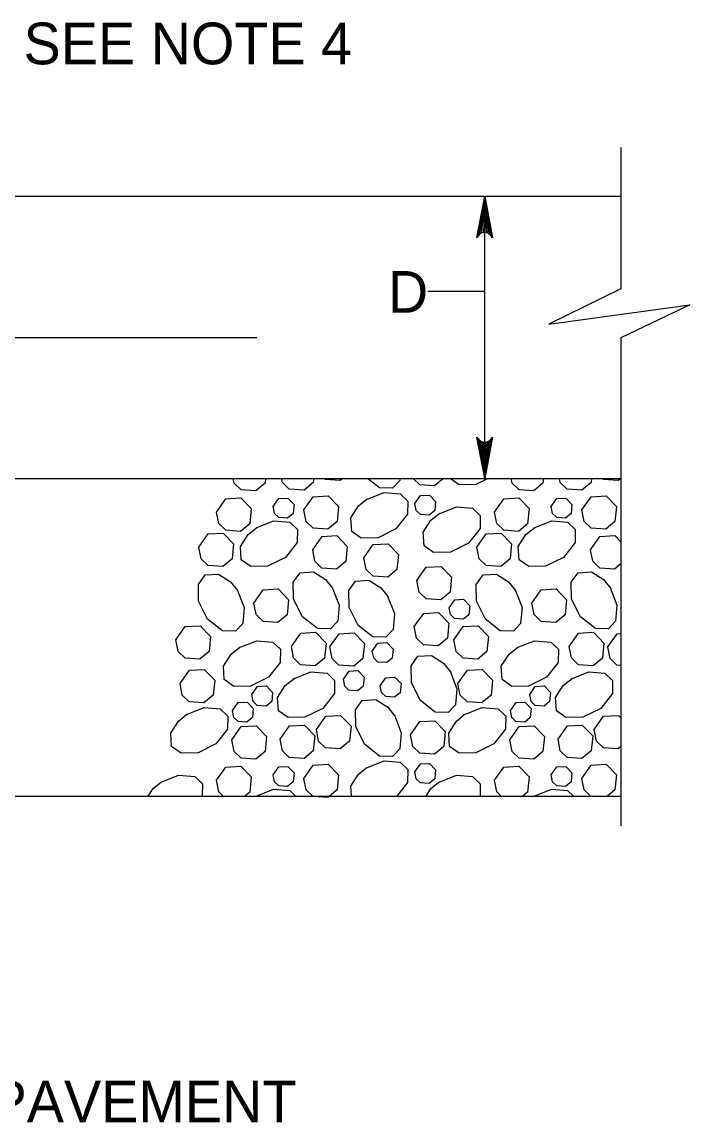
# Model space of a CAD drawing. Extents: x 2084213 to 2099800, y 976677 to 981262.
# Drawn here: x 2095747 to 2095904.6, y 979121.1 to 979381.1 of the extents above; entities that cross this region are included whole.
import ezdxf

# ---------------------------------------------------------------- set-up
doc = ezdxf.new("R2010")
doc.units = 0
doc.layers.add('1', color=7, linetype='Continuous')

msp = doc.modelspace()

# ---------------------------------------------------------------- linework, layer by layer
at = {"layer": '1'}
for p, q in [((2095888.3, 979351.47), (2095888.3, 979318.12)), ((2095516.44, 979339.99), (2095888.3, 979339.99)), ((2095856.17, 979273.33), (2095856.17, 979339.99)), ((2095856.17, 979317.49), (2095842.7, 979317.47)), ((2095602.37, 979306.66), (2095802.37, 979306.66)), ((2095888.3, 979306.58), (2095888.3, 979191.31)), ((2095516.44, 979273.33), (2095888.3, 979273.33)), ((2095516.44, 979198.33), (2095888.3, 979198.33))]:
    msp.add_line(p, q, dxfattribs=at)
for points in [[(2095856.17, 979339.99), (2095858, 979330.2), (2095857.74, 979330.58), (2095857.48, 979330.96), (2095857.15, 979331.15), (2095856.82, 979331.35), (2095856.49, 979331.4), (2095856.17, 979331.46), (2095855.84, 979331.4), (2095855.51, 979331.35), (2095855.18, 979331.15), (2095854.85, 979330.96), (2095854.59, 979330.58), (2095854.33, 979330.2), (2095856.17, 979339.99), (2095854.59, 979330.58), (2095854.85, 979330.96), (2095856.17, 979339.99), (2095855.18, 979331.15), (2095855.51, 979331.35), (2095856.17, 979339.99), (2095855.84, 979331.4), (2095856.17, 979331.46), (2095856.17, 979339.99), (2095856.49, 979331.4), (2095856.82, 979331.35), (2095856.17, 979339.99), (2095857.15, 979331.15), (2095857.48, 979330.96), (2095856.17, 979339.99), (2095857.74, 979330.58)], [(2095888.3, 979318.12), (2095871.29, 979309.8), (2095904.59, 979314.33), (2095888.3, 979306.58)], [(2095856.17, 979273.33), (2095854.33, 979283.11), (2095854.59, 979282.74), (2095854.85, 979282.36), (2095855.18, 979282.17), (2095855.51, 979281.97), (2095855.84, 979281.91), (2095856.17, 979281.86), (2095856.49, 979281.91), (2095856.82, 979281.97), (2095857.15, 979282.17), (2095857.48, 979282.36), (2095857.74, 979282.74), (2095858, 979283.11), (2095856.17, 979273.33), (2095857.74, 979282.74), (2095857.48, 979282.36), (2095856.17, 979273.33), (2095857.15, 979282.17), (2095856.82, 979281.97), (2095856.17, 979273.33), (2095856.49, 979281.91), (2095856.17, 979281.86), (2095856.17, 979273.33), (2095855.84, 979281.91), (2095855.51, 979281.97), (2095856.17, 979273.33), (2095855.18, 979282.17), (2095854.85, 979282.36), (2095856.17, 979273.33), (2095854.59, 979282.74)], [(2095804.43, 979273.33), (2095804.32, 979272.22), (2095802.15, 979270.41), (2095798.67, 979270.67), (2095797.03, 979272.25), (2095796.82, 979273.33)], [(2095815.8, 979273.33), (2095815.7, 979272.35), (2095813.53, 979270.54), (2095810.05, 979270.8), (2095808.41, 979272.38), (2095808.23, 979273.33)], [(2095822.66, 979273.33), (2095822.08, 979272.85), (2095818.6, 979273.1), (2095818.37, 979273.33)], [(2095836.19, 979273.33), (2095836.14, 979272.86), (2095834.43, 979271.05), (2095831.36, 979271.11), (2095828.52, 979273.33)], [(2095846.42, 979273.33), (2095844.32, 979271.58), (2095840.84, 979271.83), (2095839.3, 979273.33)], [(2095856.96, 979273.33), (2095854.1, 979271.89), (2095850.11, 979271.82), (2095848, 979273.33)], [(2095870.01, 979273.33), (2095869.9, 979272.22), (2095867.73, 979270.41), (2095864.25, 979270.67), (2095862.61, 979272.25), (2095862.4, 979273.33)], [(2095881.38, 979273.33), (2095881.28, 979272.35), (2095879.11, 979270.54), (2095875.63, 979270.8), (2095873.99, 979272.38), (2095873.81, 979273.33)], [(2095888.24, 979273.33), (2095887.66, 979272.85), (2095884.18, 979273.1), (2095883.95, 979273.33)], [(2095792.88, 979265.41), (2095795.09, 979268.55), (2095798.61, 979268.75), (2095801.06, 979266.22), (2095800.7, 979262.66), (2095798.53, 979260.85), (2095795.05, 979261.1), (2095793.42, 979262.69), (2095792.88, 979265.41)], [(2095806.27, 979266.71), (2095807.59, 979268.59), (2095809.7, 979268.71), (2095811.17, 979267.18), (2095810.96, 979265.05), (2095809.65, 979263.97), (2095807.57, 979264.12), (2095806.59, 979265.07), (2095806.27, 979266.7)], [(2095813.49, 979265.89), (2095815.7, 979269.03), (2095819.22, 979269.23), (2095821.67, 979266.69), (2095821.31, 979263.14), (2095819.14, 979261.33), (2095815.66, 979261.58), (2095814.03, 979263.16), (2095813.5, 979265.89)], [(2095828.29, 979268.4), (2095832.42, 979270.04), (2095836.21, 979269.71), (2095838.01, 979268), (2095837.96, 979264.92), (2095835.22, 979261.43), (2095831, 979259.31), (2095827.01, 979259.24), (2095824.77, 979260.84), (2095824.56, 979264.01), (2095826.38, 979266.85), (2095828.46, 979268.51)], [(2095839.68, 979267.43), (2095841, 979269.31), (2095843.12, 979269.43), (2095844.58, 979267.91), (2095844.37, 979265.78), (2095843.07, 979264.69), (2095840.98, 979264.84), (2095840, 979265.79), (2095839.68, 979267.43)], [(2095858.46, 979265.41), (2095860.67, 979268.55), (2095864.19, 979268.75), (2095866.64, 979266.22), (2095866.28, 979262.66), (2095864.11, 979260.85), (2095860.63, 979261.1), (2095859, 979262.69), (2095858.46, 979265.41)], [(2095871.84, 979266.71), (2095873.17, 979268.59), (2095875.28, 979268.71), (2095876.75, 979267.18), (2095876.54, 979265.05), (2095875.23, 979263.97), (2095873.15, 979264.12), (2095872.16, 979265.07), (2095871.85, 979266.7)], [(2095879.07, 979265.89), (2095881.28, 979269.03), (2095884.8, 979269.23), (2095887.25, 979266.69), (2095886.89, 979263.14), (2095884.72, 979261.33), (2095881.24, 979261.58), (2095879.61, 979263.16), (2095879.08, 979265.89)], [(2095845.39, 979265.01), (2095849.52, 979266.65), (2095853.31, 979266.32), (2095855.11, 979264.61), (2095855.06, 979261.53), (2095852.32, 979258.04), (2095848.1, 979255.93), (2095844.11, 979255.86), (2095841.87, 979257.45), (2095841.66, 979260.62), (2095843.48, 979263.46), (2095845.56, 979265.12)], [(2095802.23, 979261.68), (2095806.36, 979263.31), (2095810.15, 979262.99), (2095811.95, 979261.27), (2095811.89, 979258.2), (2095809.16, 979254.7), (2095804.93, 979252.59), (2095800.95, 979252.52), (2095798.71, 979254.11), (2095798.5, 979257.29), (2095800.32, 979260.12), (2095802.4, 979261.78)], [(2095867.81, 979261.68), (2095871.94, 979263.31), (2095875.73, 979262.99), (2095877.53, 979261.27), (2095877.47, 979258.2), (2095874.74, 979254.7), (2095870.51, 979252.59), (2095866.53, 979252.52), (2095864.29, 979254.11), (2095864.08, 979257.29), (2095865.89, 979260.12), (2095867.98, 979261.78)], [(2095788.73, 979257.11), (2095790.94, 979260.25), (2095794.46, 979260.45), (2095796.91, 979257.91), (2095796.55, 979254.36), (2095794.38, 979252.55), (2095790.9, 979252.8), (2095789.27, 979254.39), (2095788.73, 979257.11)], [(2095854.31, 979257.11), (2095856.52, 979260.25), (2095860.04, 979260.45), (2095862.49, 979257.91), (2095862.13, 979254.36), (2095859.96, 979252.55), (2095856.48, 979252.8), (2095854.85, 979254.39), (2095854.31, 979257.11)], [(2095815.57, 979256.5), (2095817.77, 979259.64), (2095821.3, 979259.84), (2095823.74, 979257.3), (2095823.39, 979253.74), (2095821.21, 979251.93), (2095817.74, 979252.18), (2095816.1, 979253.77), (2095815.57, 979256.5)], [(2095827.63, 979254.58), (2095829.83, 979257.71), (2095833.36, 979257.92), (2095835.8, 979255.38), (2095835.45, 979251.82), (2095833.27, 979250.01), (2095829.8, 979250.26), (2095828.16, 979251.85), (2095827.63, 979254.58)], [(2095881.15, 979256.5), (2095883.35, 979259.64), (2095886.88, 979259.84), (2095888.3, 979258.36)], [(2095888.3, 979253.19), (2095886.79, 979251.93), (2095883.32, 979252.18), (2095881.68, 979253.77), (2095881.15, 979256.5)], [(2095840.17, 979249.24), (2095842.37, 979252.38), (2095845.89, 979252.58), (2095848.34, 979250.04), (2095847.99, 979246.49), (2095845.81, 979244.68), (2095842.34, 979244.93), (2095840.7, 979246.52), (2095840.17, 979249.24)], [(2095797.74, 979247.03), (2095799.38, 979242.9), (2095799.05, 979239.11), (2095797.34, 979237.31), (2095794.26, 979237.37), (2095790.77, 979240.1), (2095788.66, 979244.33), (2095788.59, 979248.31), (2095790.18, 979250.55), (2095793.35, 979250.76), (2095796.19, 979248.94), (2095797.85, 979246.86)], [(2095820.16, 979247.56), (2095821.8, 979243.43), (2095821.47, 979239.64), (2095819.75, 979237.84), (2095816.68, 979237.9), (2095813.18, 979240.63), (2095811.07, 979244.86), (2095811, 979248.84), (2095812.59, 979251.08), (2095815.77, 979251.3), (2095818.6, 979249.48), (2095820.26, 979247.39)], [(2095863.32, 979247.03), (2095864.96, 979242.9), (2095864.63, 979239.11), (2095862.92, 979237.31), (2095859.84, 979237.37), (2095856.35, 979240.1), (2095854.23, 979244.33), (2095854.16, 979248.31), (2095855.76, 979250.55), (2095858.93, 979250.76), (2095861.77, 979248.94), (2095863.43, 979246.86)], [(2095885.74, 979247.56), (2095887.37, 979243.43), (2095887.05, 979239.64), (2095885.33, 979237.84), (2095882.26, 979237.9), (2095878.76, 979240.63), (2095876.65, 979244.86), (2095876.58, 979248.84), (2095878.17, 979251.08), (2095881.35, 979251.3), (2095884.18, 979249.48), (2095885.84, 979247.39)], [(2095833.24, 979245.56), (2095834.87, 979241.43), (2095834.54, 979237.64), (2095832.83, 979235.84), (2095829.76, 979235.9), (2095826.26, 979238.63), (2095824.15, 979242.86), (2095824.08, 979246.84), (2095825.67, 979249.08), (2095828.84, 979249.29), (2095831.68, 979247.48), (2095833.34, 979245.39)], [(2095801.71, 979243.91), (2095803.91, 979247.04), (2095807.43, 979247.24), (2095809.88, 979244.71), (2095809.53, 979241.15), (2095807.35, 979239.34), (2095803.87, 979239.59), (2095802.24, 979241.18), (2095801.71, 979243.91)], [(2095847.75, 979242.81), (2095849.07, 979244.7), (2095851.18, 979244.82), (2095852.65, 979243.29), (2095852.44, 979241.16), (2095851.13, 979240.07), (2095849.05, 979240.23), (2095848.07, 979241.18), (2095847.75, 979242.81)], [(2095867.28, 979243.91), (2095869.49, 979247.04), (2095873.01, 979247.24), (2095875.46, 979244.71), (2095875.11, 979241.15), (2095872.93, 979239.34), (2095869.45, 979239.59), (2095867.82, 979241.18), (2095867.29, 979243.91)], [(2095839.55, 979238.35), (2095841.76, 979241.48), (2095845.28, 979241.69), (2095847.73, 979239.15), (2095847.37, 979235.59), (2095845.2, 979233.78), (2095841.72, 979234.03), (2095840.08, 979235.62), (2095839.55, 979238.35)], [(2095783.29, 979235.23), (2095785.5, 979238.37), (2095789.02, 979238.57), (2095791.47, 979236.03), (2095791.11, 979232.48), (2095788.94, 979230.67), (2095785.46, 979230.92), (2095783.82, 979232.5), (2095783.29, 979235.23)], [(2095810.53, 979233.68), (2095812.74, 979236.82), (2095816.26, 979237.02), (2095818.71, 979234.48), (2095818.35, 979230.92), (2095816.18, 979229.11), (2095812.7, 979229.36), (2095811.07, 979230.95), (2095810.53, 979233.68)], [(2095819.61, 979233.54), (2095821.81, 979236.68), (2095825.33, 979236.88), (2095827.78, 979234.34), (2095827.43, 979230.79), (2095825.25, 979228.98), (2095821.77, 979229.23), (2095820.14, 979230.82), (2095819.61, 979233.54)], [(2095848.87, 979235.23), (2095851.08, 979238.37), (2095854.6, 979238.57), (2095857.05, 979236.03), (2095856.69, 979232.48), (2095854.52, 979230.67), (2095851.04, 979230.92), (2095849.4, 979232.5), (2095848.87, 979235.23)], [(2095876.11, 979233.68), (2095878.32, 979236.82), (2095881.84, 979237.02), (2095884.29, 979234.48), (2095883.93, 979230.92), (2095881.76, 979229.11), (2095878.28, 979229.36), (2095876.64, 979230.95), (2095876.11, 979233.68)], [(2095798.23, 979233.39), (2095802.35, 979235.03), (2095806.15, 979234.7), (2095807.95, 979232.99), (2095807.89, 979229.91), (2095805.16, 979226.42), (2095800.93, 979224.3), (2095796.95, 979224.23), (2095794.71, 979225.83), (2095794.49, 979229), (2095796.31, 979231.83), (2095798.39, 979233.5)], [(2095829.64, 979232.58), (2095830.96, 979234.46), (2095833.08, 979234.58), (2095834.55, 979233.05), (2095834.33, 979230.92), (2095833.03, 979229.84), (2095830.94, 979229.99), (2095829.96, 979230.94), (2095829.64, 979232.57)], [(2095863.81, 979233.39), (2095867.93, 979235.03), (2095871.72, 979234.7), (2095873.53, 979232.99), (2095873.47, 979229.91), (2095870.73, 979226.42), (2095866.51, 979224.3), (2095862.53, 979224.23), (2095860.28, 979225.83), (2095860.07, 979229), (2095861.89, 979231.83), (2095863.97, 979233.5)], [(2095885.18, 979233.54), (2095887.39, 979236.68), (2095888.3, 979236.73)], [(2095888.3, 979229.16), (2095887.35, 979229.23), (2095885.72, 979230.82), (2095885.19, 979233.54)], [(2095847.98, 979227.81), (2095849.61, 979223.69), (2095849.29, 979219.9), (2095847.57, 979218.1), (2095844.5, 979218.15), (2095841, 979220.89), (2095838.89, 979225.11), (2095838.82, 979229.09), (2095840.41, 979231.34), (2095843.59, 979231.55), (2095846.42, 979229.73), (2095848.08, 979227.65)], [(2095784.27, 979224.91), (2095786.48, 979228.05), (2095790, 979228.25), (2095792.45, 979225.71), (2095792.09, 979222.15), (2095789.92, 979220.34), (2095786.44, 979220.6), (2095784.81, 979222.18), (2095784.27, 979224.91)], [(2095811.03, 979226.02), (2095815.16, 979227.66), (2095818.95, 979227.33), (2095820.75, 979225.62), (2095820.69, 979222.54), (2095817.96, 979219.04), (2095813.73, 979216.93), (2095809.75, 979216.86), (2095807.51, 979218.45), (2095807.3, 979221.63), (2095809.11, 979224.46), (2095811.2, 979226.13)], [(2095822.81, 979225.95), (2095824.14, 979227.84), (2095826.25, 979227.96), (2095827.72, 979226.44), (2095827.51, 979224.3), (2095826.2, 979223.22), (2095824.12, 979223.37), (2095823.13, 979224.32), (2095822.82, 979225.95)], [(2095849.85, 979224.91), (2095852.06, 979228.05), (2095855.58, 979228.25), (2095858.03, 979225.71), (2095857.67, 979222.15), (2095855.5, 979220.34), (2095852.02, 979220.6), (2095850.38, 979222.18), (2095849.85, 979224.91)], [(2095876.61, 979226.02), (2095880.74, 979227.66), (2095884.53, 979227.33), (2095886.33, 979225.62), (2095886.27, 979222.54), (2095883.54, 979219.04), (2095879.31, 979216.93), (2095875.33, 979216.86), (2095873.09, 979218.45), (2095872.87, 979221.63), (2095874.69, 979224.46), (2095876.78, 979226.13)], [(2095801.2, 979222.34), (2095802.52, 979224.22), (2095804.64, 979224.34), (2095806.1, 979222.82), (2095805.89, 979220.68), (2095804.59, 979219.6), (2095802.5, 979219.75), (2095801.52, 979220.7), (2095801.2, 979222.34)], [(2095831.5, 979224.4), (2095832.83, 979226.29), (2095834.94, 979226.41), (2095836.41, 979224.88), (2095836.2, 979222.75), (2095834.89, 979221.66), (2095832.8, 979221.82), (2095831.82, 979222.77), (2095831.5, 979224.4)], [(2095866.78, 979222.34), (2095868.1, 979224.22), (2095870.21, 979224.34), (2095871.68, 979222.82), (2095871.47, 979220.68), (2095870.16, 979219.6), (2095868.08, 979219.75), (2095867.1, 979220.7), (2095866.78, 979222.34)], [(2095785.81, 979217.61), (2095789.94, 979219.25), (2095793.73, 979218.92), (2095795.53, 979217.21), (2095795.47, 979214.13), (2095792.74, 979210.64), (2095788.52, 979208.53), (2095784.53, 979208.46), (2095782.29, 979210.05), (2095782.08, 979213.22), (2095783.9, 979216.06), (2095785.98, 979217.72)], [(2095796.65, 979218.51), (2095797.97, 979220.39), (2095800.08, 979220.51), (2095801.55, 979218.99), (2095801.34, 979216.86), (2095800.04, 979215.77), (2095797.95, 979215.92), (2095796.97, 979216.87), (2095796.65, 979218.51)], [(2095834.84, 979217.4), (2095836.47, 979213.28), (2095836.14, 979209.49), (2095834.43, 979207.69), (2095831.36, 979207.74), (2095827.86, 979210.48), (2095825.75, 979214.7), (2095825.68, 979218.69), (2095827.27, 979220.93), (2095830.44, 979221.14), (2095833.28, 979219.32), (2095834.94, 979217.24)], [(2095851.39, 979217.61), (2095855.52, 979219.25), (2095859.31, 979218.92), (2095861.11, 979217.21), (2095861.05, 979214.13), (2095858.32, 979210.64), (2095854.1, 979208.53), (2095850.11, 979208.46), (2095847.87, 979210.05), (2095847.66, 979213.22), (2095849.48, 979216.06), (2095851.56, 979217.72)], [(2095862.23, 979218.51), (2095863.55, 979220.39), (2095865.66, 979220.51), (2095867.13, 979218.99), (2095866.92, 979216.86), (2095865.61, 979215.77), (2095863.53, 979215.92), (2095862.55, 979216.87), (2095862.23, 979218.51)], [(2095816.43, 979214.04), (2095818.64, 979217.18), (2095822.16, 979217.38), (2095824.61, 979214.84), (2095824.26, 979211.29), (2095822.08, 979209.48), (2095818.6, 979209.73), (2095816.97, 979211.32), (2095816.44, 979214.04)], [(2095838.67, 979212.78), (2095840.88, 979215.92), (2095844.4, 979216.12), (2095846.85, 979213.58), (2095846.5, 979210.02), (2095844.32, 979208.21), (2095840.84, 979208.46), (2095839.21, 979210.05), (2095838.68, 979212.78)], [(2095882.01, 979214.04), (2095884.22, 979217.18), (2095887.74, 979217.38), (2095888.3, 979216.8)], [(2095796.5, 979211.61), (2095798.71, 979214.75), (2095802.23, 979214.95), (2095804.68, 979212.41), (2095804.32, 979208.86), (2095802.15, 979207.05), (2095798.67, 979207.3), (2095797.03, 979208.89), (2095796.5, 979211.61)], [(2095807.88, 979211.74), (2095810.09, 979214.88), (2095813.61, 979215.08), (2095816.06, 979212.54), (2095815.7, 979208.99), (2095813.53, 979207.18), (2095810.05, 979207.43), (2095808.41, 979209.02), (2095807.88, 979211.74)], [(2095862.08, 979211.61), (2095864.29, 979214.75), (2095867.81, 979214.95), (2095870.26, 979212.41), (2095869.9, 979208.86), (2095867.73, 979207.05), (2095864.25, 979207.3), (2095862.61, 979208.89), (2095862.08, 979211.61)], [(2095873.46, 979211.74), (2095875.67, 979214.88), (2095879.19, 979215.08), (2095881.63, 979212.54), (2095881.28, 979208.99), (2095879.11, 979207.18), (2095875.63, 979207.43), (2095873.99, 979209.02), (2095873.46, 979211.74)], [(2095888.3, 979210.01), (2095887.66, 979209.48), (2095884.18, 979209.73), (2095882.55, 979211.32), (2095882.02, 979214.04)], [(2095813.49, 979202.52), (2095815.7, 979205.66), (2095819.22, 979205.86), (2095821.67, 979203.33), (2095821.31, 979199.77), (2095819.14, 979197.96), (2095815.66, 979198.21), (2095814.03, 979199.8), (2095813.5, 979202.52)], [(2095828.29, 979205.03), (2095832.42, 979206.67), (2095836.21, 979206.34), (2095838.01, 979204.63), (2095837.96, 979201.55), (2095835.43, 979198.33)], [(2095839.68, 979204.06), (2095841, 979205.94), (2095843.12, 979206.06), (2095844.58, 979204.54), (2095844.37, 979202.41), (2095843.07, 979201.32), (2095840.98, 979201.47), (2095840, 979202.43), (2095839.68, 979204.06)], [(2095879.07, 979202.52), (2095881.28, 979205.66), (2095884.8, 979205.86), (2095887.25, 979203.33), (2095886.89, 979199.77), (2095885.16, 979198.33)], [(2095779.82, 979201.65), (2095783.94, 979203.28), (2095787.73, 979202.95), (2095789.53, 979201.24), (2095789.48, 979198.33)], [(2095792.88, 979202.05), (2095795.09, 979205.19), (2095798.61, 979205.39), (2095801.06, 979202.85), (2095800.7, 979199.29), (2095799.55, 979198.33)], [(2095806.27, 979203.34), (2095807.59, 979205.22), (2095809.7, 979205.34), (2095811.17, 979203.82), (2095810.96, 979201.68), (2095809.65, 979200.6), (2095807.57, 979200.75), (2095806.59, 979201.7), (2095806.27, 979203.34)], [(2095824.72, 979198.33), (2095824.56, 979200.64), (2095826.38, 979203.48), (2095828.46, 979205.14)], [(2095845.39, 979201.65), (2095849.52, 979203.28), (2095853.31, 979202.95), (2095855.11, 979201.24), (2095855.06, 979198.33)], [(2095858.46, 979202.05), (2095860.67, 979205.19), (2095864.19, 979205.39), (2095866.64, 979202.85), (2095866.28, 979199.29), (2095865.13, 979198.33)], [(2095871.84, 979203.34), (2095873.17, 979205.22), (2095875.28, 979205.34), (2095876.75, 979203.82), (2095876.54, 979201.68), (2095875.23, 979200.6), (2095873.15, 979200.75), (2095872.16, 979201.7), (2095871.85, 979203.34)], [(2095776.77, 979198.33), (2095777.9, 979200.09), (2095779.98, 979201.75)], [(2095794.44, 979198.33), (2095793.42, 979199.32), (2095792.88, 979202.05)], [(2095842.35, 979198.33), (2095843.48, 979200.09), (2095845.56, 979201.75)], [(2095860.02, 979198.33), (2095859, 979199.32), (2095858.46, 979202.05)], [(2095881.12, 979198.33), (2095879.61, 979199.8), (2095879.08, 979202.52)], [(2095802.23, 979198.31), (2095806.36, 979199.95), (2095810.15, 979199.62), (2095811.5, 979198.33)], [(2095802.29, 979198.33), (2095802.4, 979198.42)], [(2095867.86, 979198.33), (2095871.94, 979199.95), (2095875.73, 979199.62), (2095877.08, 979198.33)], [(2095867.86, 979198.33), (2095867.97, 979198.42)], [(2095867.87, 979198.33), (2095867.98, 979198.42)]]:
    msp.add_lwpolyline(points, dxfattribs=at)

# ---------------------------------------------------------------- texts
for s, height, p in [('SEE NOTE 4', 9.843, (2095747.34, 979371.14)), ('D', 9.84, (2095833.32, 979312.48)), ('D = DEPTH OF CONCRETE PAVEMENT', 9.8425, (2095567.12, 979121.27))]:
    msp.add_text(s, height=height, dxfattribs=at).set_placement(p)

doc.saveas('drawing.dxf')
